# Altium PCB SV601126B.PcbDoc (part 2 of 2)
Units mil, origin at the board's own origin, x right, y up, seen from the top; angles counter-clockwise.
Board outline 2770 x 1865 mil, 4 copper layers (Top Layer, MidLayer1, MidLayer2, Bottom Layer), stack 61.2 mil thick; 102 components, 62 nets, 339 pads, 118 vias.
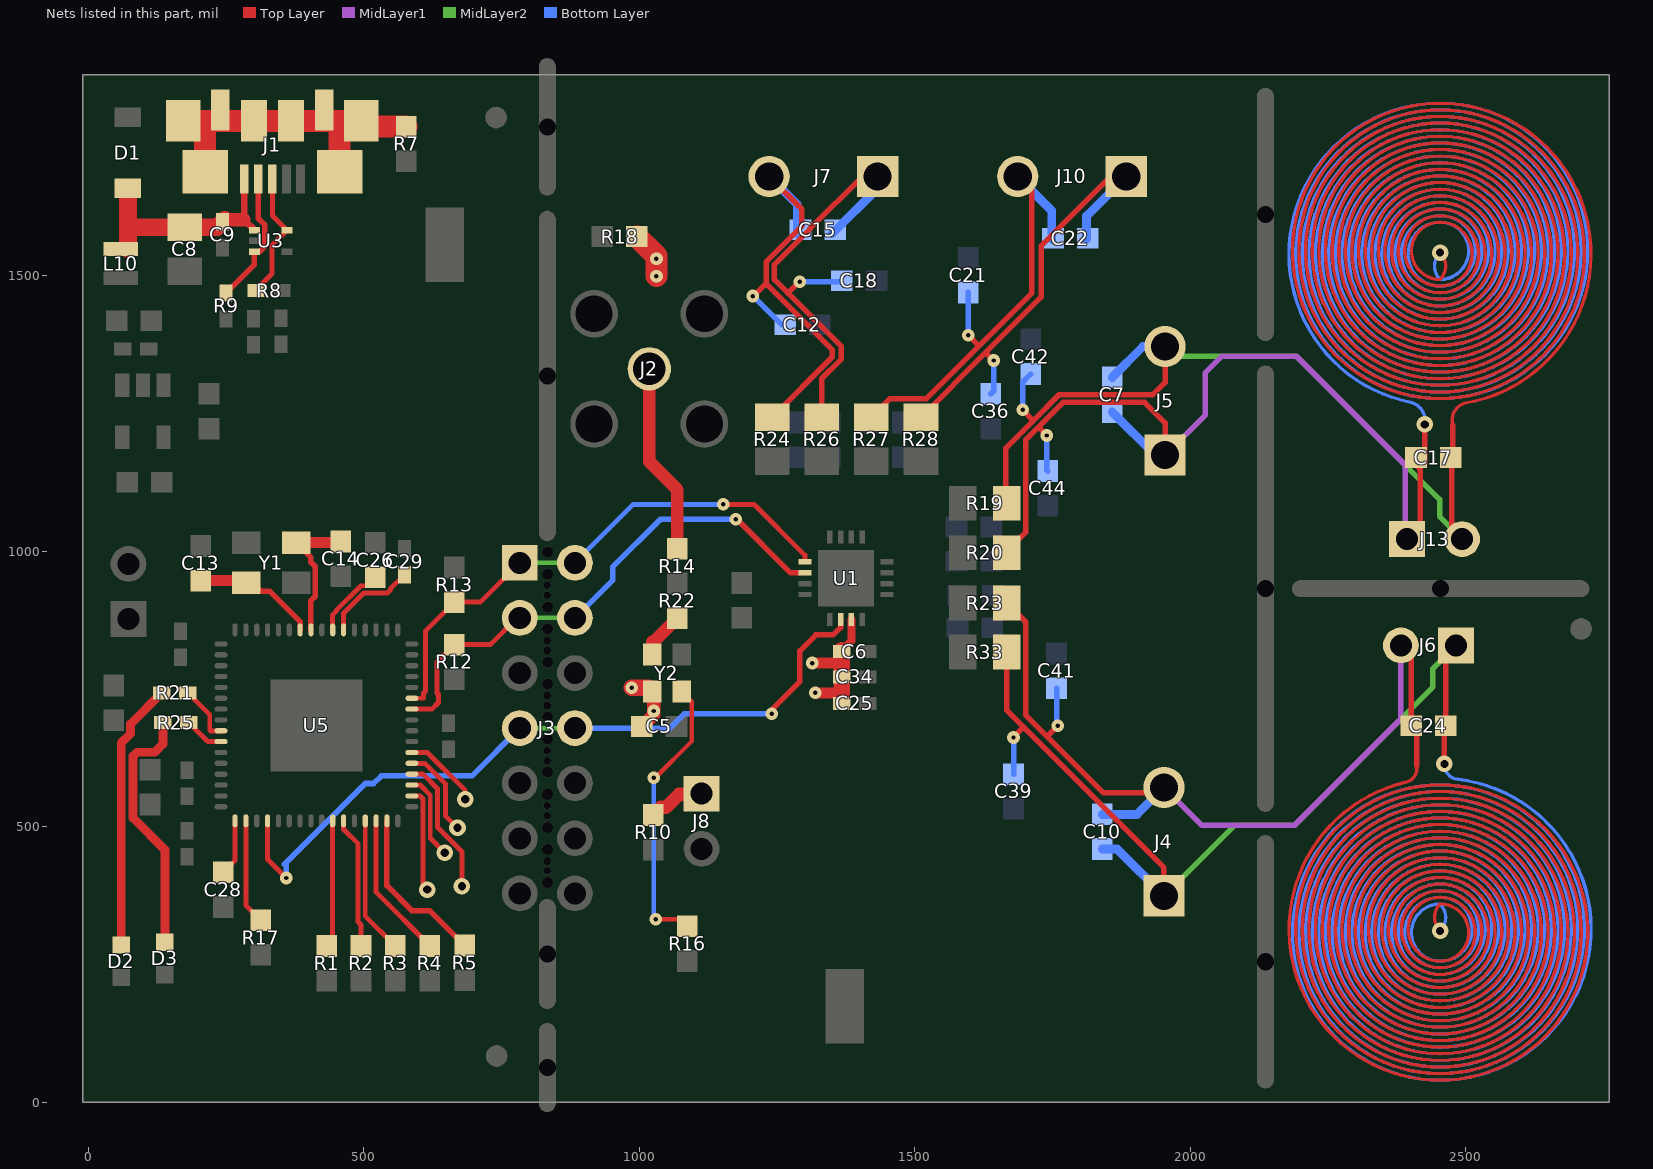
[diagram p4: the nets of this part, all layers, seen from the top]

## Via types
v1: diameter 23, hole 8, Top Layer to Bottom Layer, tented both sides, 79 vias
v2: diameter 19.68, hole 7.87, Top Layer to Bottom Layer, 18 vias
v3: diameter 20, hole 8, Top Layer to Bottom Layer, tented both sides, 8 vias
v4: diameter 30, hole 15, Top Layer to Bottom Layer, 5 vias
v5: diameter 30, hole 15, Top Layer to Bottom Layer, tented both sides, 4 vias
v6: diameter 50, hole 25, Top Layer to Bottom Layer, 2 vias
v7: diameter 50, hole 28, Top Layer to Bottom Layer, 2 vias

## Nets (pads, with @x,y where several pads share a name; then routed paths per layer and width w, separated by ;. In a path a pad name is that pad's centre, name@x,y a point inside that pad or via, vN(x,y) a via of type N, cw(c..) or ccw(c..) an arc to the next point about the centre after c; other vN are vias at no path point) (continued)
NetC7_1: C7.1 C7.2 C17.1 C17.2 C42.2 C44.1 J5.1 J5.2 J13.1 J13.2 R19.2 R20.2 | length 42477.4
  Top Layer w6: v5(2453,1542) cw(c2428.5,1517.5) 2453,1493 cw(c2453,1545) 2453,1597 cw(c2453,1539) 2453,1481 cw(c2453,1545) 2453,1609 cw(c2453,1539) 2453,1469 cw(c2453,1545) 2453,1621 cw(c2453,1539) 2453,1457 cw(c2453,1545) 2453,1633 cw(c2453,1539) 2453,1445 cw(c2453,1545) 2453,1645 cw(c2453,1539) 2453,1433 cw(c2453,1545) 2453,1657 cw(c2453,1539) 2453,1421 cw(c2453,1545) 2453,1669 cw(c2453,1539) 2453,1409 cw(c2453,1545) 2453,1681 cw(c2453,1539) 2453,1397 cw(c2453,1545) 2453,1693 cw(c2453,1539) 2453,1385 cw(c2453,1545) 2453,1705 cw(c2453,1539) 2453,1373 cw(c2453,1545) 2453,1717 cw(c2453,1539) 2453,1361 cw(c2453,1545) 2453,1729 cw(c2453,1539) 2453,1349 cw(c2453,1545) 2453,1741 cw(c2453,1539) 2453,1337 cw(c2453,1545) 2453,1753 cw(c2453,1539) 2453,1325 cw(c2453,1545) 2453,1765 cw(c2453,1539) 2453,1313 cw(c2453,1545) 2453,1777 cw(c2453,1539) 2453,1301 cw(c2453,1545) 2453,1789 cw(c2453,1539) 2453,1289 cw(c2453,1545) 2453,1801 cw(c2453,1539) 2453,1277 cw(c2453,1545) 2453,1813 cw(c2453,1539) 2498.53,1268.81 ccw(c2507.17,1237.64) 2476,1229
  Top Layer w10: R20.2@1667,997 1667,1000 1701,1034 1701,1202 1724,1225 ; R19.2@1667,1087 1665,1089 1665,1187 1716.5,1238.5 ; v1@1696,1256 1713.5,1238.5 1716.5,1238.5 ; v1(1739,1210) 1724,1225 ; J5.1@1954,1174.57 1954,1233 1917,1270 1769,1270 1724,1225 ; J5.2@1954,1371.43 1954,1306 1932,1284 1762,1284 1716.5,1238.5 ; J13.1@2392,1003 2392,1004 2417,1029 2417,1149.5 C17.1@2411.5,1155 ; C17.1@2425,1158.5 v5(2425,1230) ; J13.2@2474.5,1020.5 C17.2@2474.5,1155 ; C17.2@2476,1163.5 2476,1229 ; J13.2@2485,1010 J13.2@2492,1003
  MidLayer1 w10: J5.1@1954,1174.57 2027,1247.57 2027,1324 2057,1354 2192,1354 2390,1156 J13.1@2390,1015
  MidLayer2 w10: J5.2@1954,1371.43 1971.43,1354 2192,1354 2452,1094 2452,1063 J13.2@2493,1022
  Bottom Layer w6: v5(2425,1230) ccw(c2392.09,1237.37) 2399.45,1270.28 cw(c2453,1539) 2453,1813 cw(c2453,1545) 2453,1277 cw(c2453,1539) 2453,1801 cw(c2453,1545) 2453,1289 cw(c2453,1539) 2453,1789 cw(c2453,1545) 2453,1301 cw(c2453,1539) 2453,1777 cw(c2453,1545) 2453,1313 cw(c2453,1539) 2453,1765 cw(c2453,1545) 2453,1325 cw(c2453,1539) 2453,1753 cw(c2453,1545) 2453,1337 cw(c2453,1539) 2453,1741 cw(c2453,1545) 2453,1349 cw(c2453,1539) 2453,1729 cw(c2453,1545) 2453,1361 cw(c2453,1539) 2453,1717 cw(c2453,1545) 2453,1373 cw(c2453,1539) 2453,1705 cw(c2453,1545) 2453,1385 cw(c2453,1539) 2453,1693 cw(c2453,1545) 2453,1397 cw(c2453,1539) 2453,1681 cw(c2453,1545) 2453,1409 cw(c2453,1539) 2453,1669 cw(c2453,1545) 2453,1421 cw(c2453,1539) 2453,1657 cw(c2453,1545) 2453,1433 cw(c2453,1539) 2453,1645 cw(c2453,1545) 2453,1445 cw(c2453,1539) 2453,1633 cw(c2453,1545) 2453,1457 cw(c2453,1539) 2453,1621 cw(c2453,1545) 2453,1469 cw(c2453,1539) 2453,1609 cw(c2453,1545) 2453,1481 cw(c2453,1539) 2453,1597 cw(c2453,1545) 2453,1493 cw(c2477.5,1517.5) v5(2453,1542)
  Bottom Layer w10: v1(1696,1257) 1696,1307.5 C42.2@1710,1321.5 ; v1(1739,1210) 1739,1147.5 C44.1@1741,1145.5 ; J13.2@2476.33,1012.08 J13.2@2486,1012
  Bottom Layer w16: C7.2@1858,1252.5 1935.93,1174.57 J5.1@1954,1174.57 ; C7.1@1858,1315.5 1913.93,1371.43 J5.2@1954,1371.43
NetC10_1: C10.1 C10.2 C24.1 C24.2 C39.2 C41.1 J4.1 J4.2 J6.1 J6.2 R23.2 R33.2 | length 42470.3
  Top Layer w6: 2410.37,610.97 cw(c2385.52,605.69) 2390.8,580.85 ccw(c2453,314) 2453,40 ccw(c2453,308) 2453,576 ccw(c2453,314) 2453,52 ccw(c2453,308) 2453,564 ccw(c2453,314) 2453,64 ccw(c2453,308) 2453,552 ccw(c2453,314) 2453,76 ccw(c2453,308) 2453,540 ccw(c2453,314) 2453,88 ccw(c2453,308) 2453,528 ccw(c2453,314) 2453,100 ccw(c2453,308) 2453,516 ccw(c2453,314) 2453,112 ccw(c2453,308) 2453,504 ccw(c2453,314) 2453,124 ccw(c2453,308) 2453,492 ccw(c2453,314) 2453,136 ccw(c2453,308) 2453,480 ccw(c2453,314) 2453,148 ccw(c2453,308) 2453,468 ccw(c2453,314) 2453,160 ccw(c2453,308) 2453,456 ccw(c2453,314) 2453,172 ccw(c2453,308) 2453,444 ccw(c2453,314) 2453,184 ccw(c2453,308) 2453,432 ccw(c2453,314) 2453,196 ccw(c2453,308) 2453,420 ccw(c2453,314) 2453,208 ccw(c2453,308) 2453,408 ccw(c2453,314) 2453,220 ccw(c2453,308) 2453,396 ccw(c2453,314) 2453,232 ccw(c2453,308) 2453,384 ccw(c2453,314) 2453,244 ccw(c2453,308) 2453,372 ccw(c2453,314) 2453,256 ccw(c2453,308) 2453,360 ccw(c2477.5,335.5) v5(2453,311)
  Top Layer w10: R33.2@1667,817 1667,711 1698,680 ; R23.2@1667,906 1701,872 1701,703 1740,664 ; v1@1679,663 1696,680 1698,680 ; v1(1759,683) 1740,664 ; J4.2@1938,571.43 1938,561.53 J4.2@1942.1,561.53 ; J4.1@1952,380 1952,426 1698,680 ; J4.2@1952,571.43 J4.2@1952,576 ; J4.2@1957.8,557.43 1942.1,557.43 J4.2@1942.1,561.53 ; J6.2@2382,829 2400.5,810.5 C24.1@2400.5,684 ; 2410.37,610.97 C24.1@2410.37,673.14 ; v5(2461,614) C24.2@2461,681.5 ; C24.2@2463.5,683 2463.5,684 2463.5,810.5 J6.1@2482,829 ; 1740,664 1842.47,561.53 J4.2@1942.1,561.53
  MidLayer1 w10: J4.2@1952,571.43 2021,502.43 2188.43,502.43 2382,696 J6.2@2382,829
  MidLayer2 w10: J4.1@1952,374.57 2079.85,502.43 2188.43,502.43 2440,754 2440,787 J6.1@2482,829
  Bottom Layer w6: v5(2453,311) ccw(c2428.5,335.5) 2453,360 ccw(c2453,308) 2453,256 ccw(c2453,314) 2453,372 ccw(c2453,308) 2453,244 ccw(c2453,314) 2453,384 ccw(c2453,308) 2453,232 ccw(c2453,314) 2453,396 ccw(c2453,308) 2453,220 ccw(c2453,314) 2453,408 ccw(c2453,308) 2453,208 ccw(c2453,314) 2453,420 ccw(c2453,308) 2453,196 ccw(c2453,314) 2453,432 ccw(c2453,308) 2453,184 ccw(c2453,314) 2453,444 ccw(c2453,308) 2453,172 ccw(c2453,314) 2453,456 ccw(c2453,308) 2453,160 ccw(c2453,314) 2453,468 ccw(c2453,308) 2453,148 ccw(c2453,314) 2453,480 ccw(c2453,308) 2453,136 ccw(c2453,314) 2453,492 ccw(c2453,308) 2453,124 ccw(c2453,314) 2453,504 ccw(c2453,308) 2453,112 ccw(c2453,314) 2453,516 ccw(c2453,308) 2453,100 ccw(c2453,314) 2453,528 ccw(c2453,308) 2453,88 ccw(c2453,314) 2453,540 ccw(c2453,308) 2453,76 ccw(c2453,314) 2453,552 ccw(c2453,308) 2453,64 ccw(c2453,314) 2453,564 ccw(c2453,308) 2453,52 ccw(c2453,314) 2453,576 ccw(c2453,308) 2453,40 ccw(c2453,314) 2486,586.01 cw(c2487.5,612.5) v5(2461,614)
  Bottom Layer w10: C39.2@1679,595.5 v1(1679,662) ; C41.1@1757,751.5 1757,685 v1(1759,683) ; J6.2@2382,829 J6.2@2396,829 ; J6.1@2464,829 J6.1@2479.28,829 ; J6.1@2480.64,830.36 J6.1@2479.28,829 ; J6.1@2482,829 J6.1@2479.28,829
  Bottom Layer w16: C10.2@1840,459.5 1867.07,459.5 J4.1@1952,374.57 ; C10.1@1840,522.5 1903.07,522.5 J4.2@1952,571.43
NetC12_2: C12.2 C15.1 J7.2 R24.2 | length 814.8
  Top Layer w10: v1@1206.76,1463 1229.88,1486.12 ; J7.2@1235.57,1680 1295,1620.57 1295,1590 1229.88,1524.88 1229.88,1486.12 ; R24.2@1241,1243 1350,1352 1350,1366 1229.88,1486.12
  Bottom Layer w10: v1(1206,1463) C12.2@1258,1411
  Bottom Layer w16: J7.2@1235.57,1680 1286.5,1629.07 C15.1@1286.5,1576
NetC13_2: C13.2 U5.58 Y1.3 | length 226.3
  Top Layer w10: Y1.3@286.72,942.58 299.11,942.58 314.44,927.26 329.64,927.26 384.46,872.43 U5.58@384.46,857.23
  Top Layer w20: C13.2@204,946.5 282.8,946.5 Y1.3@286.72,942.58
NetC14_2: C14.2 U5.57 Y1.1 | length 257.3
  Top Layer w10: Y1.1@377.28,1015.42 404.15,988.54 404.15,979.96 411.87,972.25 411.87,918.19 404.15,910.47 U5.57@404.15,857.23
  Top Layer w20: Y1.1@377.28,1015.42 455.92,1015.42 C14.2@458,1017.5
NetC15_2: C15.2 C18.1 J7.1 R26.2 | length 835.8
  Top Layer w10: v1@1289,1488 1269.5,1468.5 ; 1309,1584.2 1245,1520.2 1245,1493 1269.5,1468.5 ; 1309,1584.4 1404.6,1680 J7.1@1432.43,1680 ; R26.2@1331,1243 1331,1313.2 1366,1348.2 1366,1372 1269.5,1468.5
  Bottom Layer w10: v1(1291,1489) C18.1@1365.5,1489
  Bottom Layer w16: C15.2@1349.5,1576 1432.43,1658.93 J7.1@1432.43,1680
NetC21_2: C21.2 C22.1 J10.2 R27.2 | length 851.4
  Top Layer w10: R27.2@1421,1243 1455,1277 1521,1277 1616.5,1372.5 ; v1(1597,1392) 1615.5,1373.5 1615.5,1372.5 1616.5,1372.5 ; J10.2@1688.15,1680 1712,1656.15 1712,1468 1616.5,1372.5
  Bottom Layer w10: v1(1597,1392) C21.2@1597,1469.5
  Bottom Layer w16: J10.2@1686.57,1680 1748.5,1618.07 C22.1@1748.5,1566
NetC22_2: C22.2 C36.1 J10.1 R28.2 | length 832.1
  Top Layer w10: R28.2@1511,1243 1628.5,1360.5 ; v1@1640,1349 1628.5,1360.5 ; J10.1@1885,1680 1855,1680 1729,1554 1729,1461 1628.5,1360.5
  Bottom Layer w10: C36.1@1638,1285.5 1643,1290.5 v1(1643,1346)
  Bottom Layer w16: C22.2@1811.5,1566 1811.5,1608.07 J10.1@1883.43,1680
NetC26_2: C26.2 U5.55 | length 140.8
  Top Layer w9: U5.55@443.54,857.23 443.54,884.53 450.22,891.22 450.22,892.61 494.93,937.32 517.79,937.32 521,940.53 C26.2@521,952.5
NetC28_1: C28.1 U5.17 | length 102.3
  Top Layer w9: C28.1@245,417.5 266.5,439 266.5,510.6 U5.17@266.33,510.77
NetD2_1: D2.1 R21.2 | length 487.9
  Top Layer w16: D2.1@60,285.53 60,652.15 76.7,668.85 76.7,686.32 R21.2@133.38,743
NetD3_1: D3.1 R25.2 | length 463.6
  Top Layer w16: R25.2@135.38,689 135.38,650.13 120.43,635.18 88.33,635.18 81.3,628.15 81.3,515.85 139,458.15 139,304.53 D3.1@139,290.53
NetJ1_2: J1.2 R9.1 U3.3 | length 246.1
  Top Layer w10: R9.1@250,1468.62 301.47,1520.09 U3.3@301.47,1543.32 310.26,1543.32 320.31,1553.37 320.31,1592.32 308.41,1604.22 J1.2@308.41,1675.49
NetJ1_3: J1.3 R8.1 U3.5 | length 236.7
  Top Layer w9: R8.1@304.38,1473 304.38,1474.47 333.81,1503.91 333.81,1555.97 U3.5@360.53,1582.69 334,1609.21 J1.3@334,1675.49
NetJ1_6: J1.6 J1.7 J1.8 J1.9 J1.10 J1.11 J1.12 J1.13 R7.2 | length 725
  Top Layer w40: J1.13@178,1781 J1.8@495.42,1781 ; J1.7@211.95,1688.48 211.95,1779.95 ; 211.95,1781 J1.11@300.54,1781 J1.10@367.46,1781 ; J1.6@456.05,1688.48 456.05,1777.95 ; J1.8@505.92,1770.5 R7.2@577,1770.5
NetJ2_1: J2.1 R14.2 | length 347.6
  Top Layer w23: J2.1@1018,1331 1018,1162.5 1069,1111.5 R14.2@1069,1004.5
NetR1_1: R1.1 U5.26 | length 231.6
  Top Layer w9: R1.1@433,283.5 443.54,294.03 U5.26@443.54,510.77
NetR2_1: R2.1 U5.27 | length 240.4
  Top Layer w9: U5.27@463.22,510.77 463.22,495.57 489.61,469.19 489.61,327.11 495,321.72 R2.1@495,283.5
NetR3_1: R3.1 U5.29 | length 249.8
  Top Layer w9: U5.29@502.61,510.77 502.61,337.89 R3.1@557,283.5
NetR4_1: R4.1 U5.30 | length 267.7
  Top Layer w9: U5.30@522.3,510.77 522.3,381.2 R4.1@620,283.5
NetR5_1: R5.1 U5.31 | length 303.7
  Top Layer w10: U5.31@541.98,510.77 541.98,393.02 587,348 619.5,348 R5.1@683,284.5
NetR16_2: R16.2 Y2.1 | length 515
  Top Layer w8: v1(1026.4,588.82) 1028.71,588.82 1095.43,655.55 1095.43,726.68 Y2.1@1076.57,745.54 ; v1(1030,332) 1074.5,332 R16.2@1087,319.5
  Bottom Layer w8: v1(1026.4,588.82) 1026.4,335.6 v1(1030,332)
NetR17_1: R17.1 U5.18 | length 191.5
  Top Layer w9: U5.18@286.01,510.77 286.01,357.48 R17.1@313,330.5
NetR21_1: R21.1 U5.9 | length 104.7
  Top Layer w9: R21.1@180.62,743 220.46,703.16 220.46,675.85 222.16,674.16 U5.9@240.77,674.16
NetR22_1: R22.1 Y2.3 | length 96.8
  Top Layer w10: R22.1@1069,878.5 R22.1@1076.46,871.04
  Top Layer w23: Y2.3@1023.43,812.46 1023.43,835.15 1025.65,835.15 R22.1@1069,878.5
NetR25_1: R25.1 U5.10 | length 72.5
  Top Layer w9: R25.1@182.62,689 217.15,654.47 U5.10@240.77,654.47
P3.0: U5.34 | length 190.2
  Top Layer w9: U5.34@587.23,556.05 601.95,556.05 607.54,550.46 607.54,393.46 v4(615,386)
P3.1: U5.35 | length 156.3
  Top Layer w9: U5.35@587.23,575.73 602.27,575.73 620.54,557.46 620.54,479.46 v4(647,453)
P3.2: U5.36 | length 252.9
  Top Layer w9: U5.36@587.23,595.42 607.58,595.42 633.54,569.46 633.54,499.69 678,455.23 v4(678,392)
P3.3: U5.37 | length 165.3
  Top Layer w9: U5.37@587.23,615.1 610.9,615.1 648,578 648,520 v4(670,498)
P3.4: U5.38 | length 141.3
  Top Layer w9: U5.38@587.23,634.79 615.21,634.79 684,566 v4(684,550)
SCL: J3.1 J3.2 R13.1 U1.1 U5.43 | length 978.6
  Top Layer w9: U5.43@587.23,733.21 608.21,733.21 608.21,742.44 611.54,745.76 611.54,855.04 R13.1@664,907.5 711.5,907.5 J3.1@783,979 ; v1(1152,1085) 1208,1085 1300.2,992.8 U1.1@1300.2,980.53
  MidLayer2 w8: J3.1@783,979 J3.2@883,979
  Bottom Layer w9: J3.2@883,979 989,1085 v1(1152,1085)
SD: J3.7 J3.8 U1.6 U5.20 | length 1373.8
  Top Layer w9: U5.20@325.39,510.77 325.39,440.61 v1(359,407)
  Top Layer w10: v1(1240,705) 1240,712 1284.39,756.39 1291.2,763.2 1291.2,819 1320.2,848 1351.77,848 1365.16,861.39 U1.6@1365.16,876.2
  MidLayer2 w8: J3.7@783,679 J3.8@873,679
  Bottom Layer w10: v1(359,407) 359,429.08 356.08,432 502.58,578.5 517.8,578.5 531.8,592.5 696.5,592.5 J3.7@783,679 ; J3.8@883,679 1052,679 1053.61,677.39 1081.23,705 v1(1240,705)
SDA: J3.3 J3.4 R12.1 U1.2 U5.42 | length 948.1
  Top Layer w9: U5.42@587.23,713.53 623.53,713.53 635.46,725.46 635.46,739.98 632.8,742.64 632.8,799.3 R12.1@664,830.5 729.5,830.5 778,879 J3.3@783,879
  Top Layer w10: v1(1175,1058) 1177,1058 1274.47,960.53 U1.2@1291.2,960.53
  MidLayer2 w8: J3.3@783,879 J3.4@883,879
  Bottom Layer w10: J3.4@883,879 952,948 952,972 1038,1058 v1(1175,1058)
VBUS: C8.1 C9.1 D1.1 J1.1 L10.1 U3.1 | length 429.4
  Top Layer w12: J1.1@282.82,1675.49 282.82,1601.34 U3.1@301.47,1582.69
  Top Layer w24: C9.1@247.72,1601.34 282.82,1601.34
  Top Layer w32: L10.1@71,1548.57 72,1549.57 72,1593.32 ; D1.1@72,1658.53 72,1593.32 ; C9.1@247.72,1601.34 C9.1@244,1597.62 234.38,1588 C8.1@175,1588 77.32,1588 72,1593.32
VDD: C5.1 C6.1 C25.1 C34.1 J8.1 R10.2 R18.2 U1.7 Y2.4 | length 547.1
  Top Layer w14: C6.1@1367.38,820 1384.84,837.46 U1.7@1384.84,876.2
  Top Layer w20: v1(1314,797) 1364.88,797 1367.38,799.5 ; v1(1319,743) 1365.88,743 1367.38,744.5
  Top Layer w24: C5.1@1004.5,682 1026,703.5 1026,742.96 Y2.4@1023.43,745.54 ; R10.2@1025,521.5 1038.83,535.32 1048.56,535.32 1072.42,559.18 1113,559.18 J8.1@1113,560
  Top Layer w30: v1(986,752) 1016.96,752 Y2.4@1023.43,745.54 ; 1367.38,744.5 C34.1@1367.38,772 1367.38,799.5 C6.1@1367.38,820
  Top Layer w40: R18.2@995.5,1571 1031,1535.5 v1(1031,1499)
  other v1: 1026,710 1031,1530.77
VUSB: C29.1 U5.54 | length 171.2
  Top Layer w9: U5.54@463.22,857.23 463.22,887.22 500.32,924.32 543.22,924.32 548.2,929.3 548.2,931.58 C29.1@574,957.38
pads on no net: FID1.1 FID2.1 FID3.1 J1.4 LBL1.0 U3.2 U5.1 U5.2 U5.3 U5.4 U5.5 U5.6 U5.7 U5.8 U5.12 U5.13 U5.22 U5.23 U5.24 U5.25 U5.28 U5.32 U5.33 U5.41 U5.44 U5.45 U5.46 U5.47 U5.48

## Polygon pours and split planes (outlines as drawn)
GND on MidLayer1 "Bottom Layer-No Net" (solid, pour order 9): 20,20 793,20 793,1840 20,1840 20,20
GND on MidLayer1 "Bottom Layer-No Net" (solid, remove dead copper, pour order 12): 875,35 2100,35 2100,1840 875,1840 875,35
+3.3V on MidLayer2 "Bottom Layer-No Net" (solid, pour order 7): 20,770 790,770 790,1840 20,1840
+3.3V on MidLayer2 "Bottom Layer-No Net" (solid, pour order 8): 17,17 791,17 791,770.5 17,770.5 17,17
+3.3V on MidLayer2 "Bottom Layer-No Net" (solid, remove dead copper, pour order 11): 875,35 2100,35 2100,1840 875,1840 875,35
VDD on MidLayer2 "Bottom Layer-No Net" (solid, remove dead copper, pour order 10): 972.46,510 1600,510 1600,1725.95 972.46,1725.95
GND on Bottom Layer "Bottom Layer-No Net 1" (solid, remove dead copper, pour order 8): 1782,1549.3 901,1549.3 901,502 1782,502

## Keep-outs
Keep-Out Layer:
  lines w8: -15,-5 2765,-5 2765,1870 -15,1870 -15,-5
  text ".Layer_Name" at 577,-858.49 h60

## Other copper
Top Layer:
  text ".Layer_Name" at 577,-858.49 h60
MidLayer1:
  pour cut-out: 154.5,894 154.7,894.2 154.7,1052.87 485.63,1052.87 497.5,1040.99 497.5,888
MidLayer2:
  pour cut-out: 866.5,1483.11 866.61,1483 1172.5,1483 1172.5,1175 1171.5,1174 866.5,1174
  pour cut-out: 154.5,894 154.7,894.2 154.7,1052.87 485.63,1052.87 497.5,1040.99 497.5,888
Bottom Layer:
  text ".Layer_Name" at 577,-858.49 h60
Multi-Layer:
  pour cut-out: 2453,-239 cw(c2453,311) 1903,311 cw(c2453,311) 2453,861 cw(c2453,311) 3003,311 cw(c2453,311)
  pour cut-out: 1903,1542 ccw(c2453,1542) 2453,992 ccw(c2453,1542) 3003,1542 ccw(c2453,1542) 2453,2092 ccw(c2453,1542)

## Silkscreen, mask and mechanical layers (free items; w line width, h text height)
Top Overlay:
  lines w10: 1223,693 1550,693 1550,1106 1223,1106 1223,693
  text "GND" at 897,1808 h30
  text "CH3" at 1274.37,1429.68 h60
  text "CH2" at 1582,1430 h60
  text "GND" at 602,1425 h30
  text "SENSOR CH1" at 2285,1264 h55 r90
  text "+5V" at 417,1165 h30
  text "LDC" at 1235,1050 h40
  text "CH1" at 1873,977 h60
  text "or" at 1010,943 h30 r90
  text "SBW" at 161,898 h25 r90
  text "+3.3V" at 1204,438 h30 r90
  text "GND" at 1338,289 h30
  text "GND" at 891,255 h30
  text "CH0" at 1864,158 h60
  text "SENSOR CH0" at 2285,64 h55 r90
  text "GND" at 179,52 h30
  text "ACLK" at 360,43 h30 r90
  text ".Layer_Name" at 577,-858.49 h60
  text "CH0" at 2292,-1832 h60
Bottom Overlay:
  region: 267,589 267,889 167,889 167,589
  text ".PRJ_Number" at 267,1805 h60 r90
  text "0.15mm trace width" at 2630,1804 h40 r90
  text "0.15mm trace spacing" at 2688,1804 h40 r90
  text "19 turns/layer" at 2514,1803 h40 r90
  text "2 layers" at 2572,1803 h40 r90
  text "SENSOR: 13.9mm" at 2456,1802 h40 r90
  text ".PCB_Rev" at 267,1292 h60 r90
  text "TCK" at 100,1042 h25
  text "SCL" at 1015,968 h30
  text "SDA" at 1024.37,865 h30
  text "TDIO" at 113,791 h25
  text "©" at 2613,768 h105 r90
  text "ADDR" at 1060.3,762 h30
  text "MADE IN U.S." at 2717,760 h60 r90
  text ".CopyrightYear" at 2086,677 h60 r90
  text "SD" at 1010,660 h30
  text "INTB" at 1045,565 h30
  text "GND" at 1018.25,469.61 h30
  text "3.3V" at 1046,363 h30
  text ".Layer_Name" at 577,-858.49 h60
Top Paste:
  text ".Layer_Name" at 577,-858.49 h60
Bottom Paste:
  text ".Layer_Name" at 577,-858.49 h60
Top Solder:
  text ".Layer_Name" at 577,-858.49 h60
  text ".Layer_Name" at 577,-858.49 h60
Bottom Solder:
  text ".Layer_Name" at 577,-858.49 h60
Drill Guide:
  text ".Layer_Name" at 577,-858.49 h60
M1 Board Outline:
  the board outline again, w8
  text ".Layer_Name" at 577,-858.49 h60
M2 Board Dimensions:
  rectangle: 124.5,-410.5 499.5,-285.5
  rectangle: -0.5,-285.5 124.5,-160.5
  lines w7: -0.5,-285.5 999.5,-285.5 ; 124.5,-410.5 124.5,-160.5 ; 249.5,-410.5 249.5,-160.5 ; 499.5,-410.5 499.5,-160.5 ; 749.5,-410.5 749.5,-160.5 ; -0.5,-410.5 -0.5,-160.5 999.5,-160.5 999.5,-410.5 -0.5,-410.5
  lines w10: -0.5,-475.5 -0.5,-455.5 ; 59.5,-485.5 -0.5,-465.5 ; 59.5,-445.5 -0.5,-465.5 ; 223.58,-465.5 -0.5,-465.5 ; 775.42,-465.5 999.5,-465.5 ; 939.5,-485.5 999.5,-465.5 ; 939.5,-445.5 999.5,-465.5 ; 999.5,-475.5 999.5,-455.5
  text "1000 (mil)" at 233.58,-501.49 h60
  text ".Layer_Name" at 577,-858.49 h60
M3 3D STEP Top:
  text ".Layer_Name" at 577,-858.49 h60
M4 3D STEP Bottom:
  text ".Layer_Name" at 577,-858.49 h60
M5 Assembly Top:
  lines w10: -292,-930.17 6308,-930.17 ; -292,-726.83 6310,-726.83 ; -292,-523.5 -292,-1133.5 3713,-1133.5 6310,-1133.5 6310,-523.5 -291.5,-523.5 -291.5,-1133.5 1284,-1133.5 ; 2173,-1133.5 2173,-523.5 ; 3440,-726.83 3440,-523.5 ; 4280,-726.83 4280,-523.5 ; 4902,-1140 4902,-937.17
  text "COMPONENTS MARKED 'DNP' SHOULD NOT BE POPULATED." at 1153.5,-318.5 h60
  text "ASSEMBLY VARIANT:" at 1153,-434 h60
  text ".VariantName" at 2189,-434 h60
  text "PCB VIEWED FROM TOP SIDE" at -228.5,-655.67 h60
  text "BOARD #:" at 2248,-655.67 h60
  text ".PRJ_Number" at 2793.5,-655.67 h60
  text "REV:" at 3638,-655.67 h60
  text ".PCB_Rev" at 3929.5,-655.67 h60
  text "SVN REV:" at 4476,-655.67 h60
  text ".VersionControl_RevNumber" at 4982,-655.67 h60
  text "IGNORE ->" at -228.5,-858.49 h60
  text "PLOT NAME =" at -228.5,-1064.34 h60
  text ".plot_File_Name" at 577,-1064.34 h60
  text "GENERATED    :" at 2250,-1064.34 h60
  text ".Print_Date" at 3119.5,-1064.34 h60
  text ".Print_Time" at 3848.5,-1064.34 h60
  text "TEXAS INSTRUMENTS" at 5113,-1064.34 h60
M6 Assembly Bottom:
  lines w10: -292.5,-727.33 6309.5,-727.33 ; -290.5,-930.67 6309.5,-930.67 ; 1115.5,-1140.5 1115.5,-937.67 ; 1737.5,-727.33 1737.5,-524 ; 2577.5,-727.33 2577.5,-524 ; 3844.5,-1134 3844.5,-524 ; 4733.5,-1134 6309,-1134 6309,-524 -292.5,-524 -292.5,-1134 2304.5,-1134 6309.5,-1134 6309.5,-524
  text "COMPONENTS MARKED 'DNP' SHOULD NOT BE POPULATED." at 6102,-318 h60
  text ".VariantName" at 5058,-434 h60
  text "ASSEMBLY VARIANT:" at 6097,-434 h60
  text ".VersionControl_RevNumber" at 1035.5,-656.17 h60
  text "SVN REV:" at 1541.5,-656.17 h60
  text ".PCB_Rev" at 2088,-656.17 h60
  text "REV:" at 2379.5,-656.17 h60
  text ".PRJ_Number" at 3224,-656.17 h60
  text "BOARD #:" at 3769.5,-656.17 h60
  text "PCB VIEWED FROM BOTTOM SIDE" at 6246,-656.17 h60
  text "IGNORE ->" at 2547.85,-858.49 h60
  text "TEXAS INSTRUMENTS" at 904.5,-1064.84 h60
  text ".Print_Time" at 2169,-1064.84 h60
  text ".Print_Date" at 2898,-1064.84 h60
  text "GENERATED    :" at 3767.5,-1064.84 h60
  text ".plot_File_Name" at 5440.5,-1064.84 h60
  text "PLOT NAME =" at 6246,-1064.84 h60
M9 Title Sheet:
  drawing of 54 lines, arcs and shapes, not listed
  text "1" at 739.84,8036.5 h70
  text "2" at 3235.5,8036.5 h70
  text "3" at 5724.84,8036.5 h70
  text "4" at 8231.51,8036.5 h70
  text "5" at 10730.5,8036.5 h70
  text "6" at 13235.5,8036.5 h70
  text "A" at -416.5,6893.5 h70
  text "A" at 14383.5,6893.5 h70
  text "B" at -416.5,4513.5 h70
  text "B" at 14383.5,4513.5 h70
  text "C" at -416.5,2138.5 h70
  text "C" at 14383.5,2138.5 h70
  text "PROJECT TITLE:" at 11343.5,277.5 h45
  text ".PRJ_Title" at 11393.5,144.17 h70
  text "DESIGNED FOR:" at 11343.5,-23.5 h45
  text ".PRJ_Customer" at 11393.5,-163.5 h70
  text "D" at -416.5,-231.5 h70
  text "D" at 14383.5,-231.5 h70
  text "FILE NAME:" at 11343.5,-323.5 h45
  text ".PCB_File_Name_No_Path" at 11393.5,-443.5 h70
  text "Texas Instruments (TI) and/or its licensors do not warrant the accuracy or completeness of this specification" at 6374,-605.34 h45
  text "ENGINEER:" at 11343.5,-613.5 h45
  text "LAYOUT BY:" at 12848.5,-613.5 h45
  text "or any information contained therein. TI and/or its licensors do not warrant that this design will meet" at 6329.01,-718 h45
  text ".PRJ_Engineer" at 11393.5,-768.49 h70
  text ".PCB_Layout" at 12899,-768.49 h70
  text "the specifications, will be suitable for your application or fit for any particular purpose, or will operate in" at 6329.01,-830.67 h45
  text ".Layer_Name" at 577,-858.49 h60
  text "ALTIUM DESIGNER VERSION:" at 12848.5,-923.5 h45
  text "an implementation. TI and/or its licensors do not warrant that the design is production worthy. You should" at 6329.01,-943.33 h45
  text "completely validate and test your design implementation to confirm the system functionality for your application." at 6374,-1056 h45
  text ".print_Scale" at 11393.5,-1056.83 h70
  text ".Application_BuildNumber" at 12899,-1056.83 h70
  text "1" at 739.84,-1263.5 h70
  text "2" at 3235.5,-1263.5 h70
  text "3" at 5724.84,-1263.5 h70
  text "4" at 8231.51,-1263.5 h70
  text "5" at 10730.5,-1263.5 h70
  text "6" at 13235.5,-1263.5 h70
M10 Fab Notes:
  drawing of 212 lines, arcs and shapes, not listed
  text "DESIGN INFORMATION" at 12381.02,6810 h60
  text "(REFER ALSO ARRAY/PANEL PROFILING INFORMATION)" at 12019.46,6648.29 h60
  text "BOARD SIZE" at 11333.46,6644 h60
  text "2760MIL" at 11795.78,6516.18 h60
  text "X" at 12301.46,6516.18 h60
  text "1865MIL" at 12532.78,6516.18 h60
  text "Number of Layers :" at 11736.46,6319 h60
  text "4" at 12831.27,6309 h60
  text "MIN. TRACK WIDTH:" at 11736.46,6180 h60
  text "4" at 12832.7,6180 h60
  text "MIL" at 12987.46,6180 h60
  text "MIN. CLEARANCE:" at 11736.46,6048 h60
  text "4" at 12832.7,6048 h60
  text "MIL" at 12987.46,6048 h60
  text "MIN. VIA PAD SIZE:" at 11736.46,5916 h60
  text "20" at 12802.71,5916 h60
  text "MIL" at 12987.46,5916 h60
  text "0.05mm (2MIL)" at 12431.46,5774.29 h60
  text "MINIMUM ANNULAR RING" at 11407.23,5770 h60
  text "EXTERNAL" at 13139.46,5770 h60
  text "PER" at 11607.23,5652 h60
  text "IPC-D-275 CLASS 2 LEVEL C" at 11827.23,5652 h60
  text "MIL, HOLES" at 13315.46,5539.71 h60
  text "+/-" at 12923,5539 h60
  text "+/-" at 13777,5539 h60
  text "REGISTRATION TOLERANCES:" at 11407.23,5534 h60
  text "METAL" at 12607,5534 h60
  text "5" at 13183.2,5534 h60
  text "3" at 14016.2,5534 h60
  text "MIL" at 14132.46,5534 h60
  text "MATERIAL:" at 11332.46,5324.54 h60
  text "FR-4 High Tg" at 12318.9,5184.21 h60
  text "FR-408" at 11753.46,5175.64 h60
  text "X" at 12165.46,5175.64 h60
  text "OTHER" at 13241.46,5175.64 h60
  text "62 MIL (1.6mm) +/-10%" at 12073.56,5012.92 h60
  text "THICKNESS:" at 11407.23,5008.64 h60
  text "X" at 11945.4,5008.64 h60
  text "OTHER" at 13358.46,5008.64 h60
  text "TOLERANCE:" at 11407.23,4850.64 h60
  text "X" at 12246.53,4850.64 h60
  text "ANSI IPC-6012 TYPE 3 CLASS 2" at 12433.48,4850.64 h60
  text "OTHER +/-" at 12433.46,4694.64 h60
  text "BOW & TWIST:" at 11407.23,4537.64 h60
  text "X" at 12246.53,4537.64 h60
  text "ANSI IPC-6012 TYPE 3 CLASS 2" at 12433.48,4537.64 h60
  text "OTHER +/-" at 12433.46,4379.13 h60
  text "COPPER THICKNESS (FINISHED):" at 11332.46,4243.64 h60
  text "1.4MIL (1oz)" at 12212.46,4090.92 h60
  text "2MIL (1.4oz)" at 12979.46,4090.92 h60
  text "2.8MIL (2oz)" at 13706.46,4090.92 h60
  text "OUTER:" at 11689.46,4086.64 h60
  text "X" at 12084,4086 h60
  text "1.4MIL (1oz)" at 12212.46,3933.92 h60
  text "2.8MIL (2oz)" at 12979.46,3933.92 h60
  text "N/A" at 13706,3934.29 h60
  text "INNER SIGNAL:" at 11400.38,3929.64 h60
  text "X" at 12085.42,3929.64 h60
  text "DRILLING:" at 11332.46,3790.64 h60
  text "REFERENCE:" at 11407.23,3673.64 h60
  text "X" at 12055.46,3673.64 h60
  text "AS SHOWN" at 12242.46,3673.64 h60
  text "X" at 12956.46,3673.64 h60
  text "NC_DRILL FILES" at 13093.46,3673.64 h60
  text "PTH MIN COPPER THICKNESS:" at 11407.23,3515.64 h60
  text "X" at 12757.46,3515.64 h60
  text "1MIL" at 12894.46,3515.64 h60
  text "OTHER" at 13391.46,3515.64 h60
  text "BOARD FINISH:" at 11332.46,3356.64 h60
  text "SILKSCREEN:" at 11487.68,3238.64 h60
  text "X" at 12436.46,3238.64 h60
  text "TOP" at 12562.46,3238.64 h60
  text "X" at 12946.46,3238.64 h60
  text "BOTTOM" at 13073.46,3238.64 h60
  text "SILKSCREEN COLOR:" at 11487.68,3071.64 h60
  text "X" at 12435.42,3071.64 h60
  text "WHITE" at 12562.46,3071.64 h60
  text "OTHER" at 13073.46,3071.64 h60
  text "SOLDER RESIST COLOR:" at 11487.68,2901.64 h60
  text "X" at 12055.42,2742.44 h60
  text "GREEN" at 12182.46,2742.44 h60
  text "BLUE" at 12773.46,2742.44 h60
  text "OTHER" at 13311.46,2742.44 h60
  text "IMMERSION GOLD (ENIG)" at 12393.46,2553.92 h60
  text "ENEPIG" at 13731,2550.64 h60
  text "SURFACE FINISH:" at 11332.46,2549.64 h60
  text "X" at 12206.51,2549.64 h60
  text "IMM. TIN/SILVER OR EQUIV" at 11662,2392.64 h60
  text "OTHER" at 13093.46,2392.64 h60
  text "ARRAY/PANEL:" at 11332.46,2213.64 h60
  text "CUT AND TRIM PER MECH LAYER 1" at 12393.46,2209.35 h60
  text "X" at 12209,2062 h60
  text "N.C. ROUTE" at 12393.46,2057.64 h60
  text "V. SCORE" at 13259.46,2057.64 h60
  text "CERTIFICATION:" at 11332.46,1920.64 h60
  text "MATERIALS AND WORKMANSHIP FOR ALL PCBS" at 12057.46,1920.64 h60
  text "TO MEET OR EXCEED THE REQUIREMENTS OF:" at 12057.46,1822.64 h60
  text "X" at 11683.96,1686.13 h60
  text "ANSI IPC-A-600F CLASS ->" at 11822.96,1686.13 h60
  text "X" at 13462.02,1686.13 h60
  text "2" at 13580.96,1686.14 h60
  text "1" at 13265.96,1684.64 h60
  text "3" at 13934.96,1684.64 h60
  text "X" at 11686.02,1526.64 h60
  text "UL 94V-0" at 11822.96,1526.64 h60
  text "X" at 12498.02,1526.64 h60
  text "RoHS" at 12634.96,1526.64 h60
  text "OTHER" at 13279.36,1526.64 h60
  text "PER ORDER" at 13676.42,1526.64 h60
  text "ADDITIONAL REQUIREMENTS:" at 11332.46,1385.64 h60
  text "MICROSECTION:" at 11407.23,1270.64 h60
  text "YES" at 12312.96,1270.64 h60
  text "REQUIRED" at 13174.46,1114.49 h60
  text "BARE BOARD ELEC. TEST:" at 11407.23,1111.64 h60
  text "NONE" at 12712.96,1111.64 h60
  text "X" at 13047.46,1111.64 h60
  text "PER ORDER" at 13766.46,1111.64 h60
  text "MANUFACTURER'S UL:" at 11407.23,954.64 h60
  text "RAIL" at 12572.96,950.35 h60
  text "METAL" at 13064.77,950.35 h60
  text "X" at 13440,950 h60
  text "SILK" at 13576.46,950.35 h60
  text ".Layer_Name" at 577,-858.49 h60
M11 Gerber Information:
  lines w10: -292,-930.17 6308,-930.17 ; -292,-726.83 6310,-726.83 ; -292,-523.5 -292,-1133.5 3713,-1133.5 6310,-1133.5 6310,-523.5 -291.5,-523.5 -291.5,-1133.5 1284,-1133.5 ; 2173,-1133.5 2173,-523.5 ; 3440,-726.83 3440,-523.5 ; 4280,-726.83 4280,-523.5 ; 4902,-1140 4902,-937.17
  text "ALL ARTWORK VIEWED FROM TOP SIDE" at -228.5,-655.67 h60
  text "BOARD #:" at 2248,-655.67 h60
  text ".PRJ_Number" at 2793.5,-655.67 h60
  text "REV:" at 3638,-655.67 h60
  text ".PCB_Rev" at 3929.5,-655.67 h60
  text "SVN REV:" at 4476,-655.67 h60
  text ".VersionControl_RevNumber" at 4982,-655.67 h60
  text "LAYER NAME =" at -228.5,-858.49 h60
  text "PLOT NAME =" at -228.5,-1064.34 h60
  text ".plot_File_Name" at 577,-1064.34 h60
  text "GENERATED    :" at 2250,-1064.34 h60
  text ".Print_Date" at 3119.5,-1064.34 h60
  text ".Print_Time" at 3848.5,-1064.34 h60
  text "TEXAS INSTRUMENTS" at 5113,-1064.34 h60
M12 Stackup:
  lines w6: 11365,7632.25 14230,7632.25 ; 11365,7744.85 14230,7744.85 ; 11286,6907 ccw(c11322,6907) 11322,6871 14235,6871 ccw(c14235,6907) 14271,6907 14271,7902 ccw(c14235,7902) 14235,7938 11322,7938 ccw(c11322,7902) 11286,7902 11286,6907
  text "Layer Stack Up Detail for: SV601147B.PcbDoc" at 11346,7819.02 h58
  text "Layer" at 11365,7702.85 h26
  text "Gerber" at 12072.2,7702.85 h26
  text "Copper" at 12433.65,7702.85 h26
  text "Dielectric" at 12837.55,7702.85 h26
  text "Dielectric" at 13259.64,7702.85 h26
  text "Dielectric" at 13786.9,7702.85 h26
  text "Name" at 11365,7650.85 h26
  text "Document" at 12072.2,7650.85 h26
  text "Thickness" at 12433.65,7650.85 h26
  text "Height" at 12837.55,7650.85 h26
  text "Material" at 13259.64,7650.85 h26
  text "Type" at 13786.9,7650.85 h26
  text "Top Solder Mask" at 11365,7573.68 h36
  text "(.GTS)" at 12072.2,7573.68 h36
  text "0.4mil" at 12837.55,7573.68 h36
  text "Solder Resist" at 13259.64,7573.68 h36
  text "Top Layer" at 11365,7462.53 h36
  text "(.GTL)" at 12072.2,7462.53 h36
  text "1.4mil" at 12433.65,7462.53 h36
  text "12.6mil" at 12837.55,7406.96 h36
  text "FR-4" at 13259.64,7406.96 h36
  text "Core" at 13786.9,7406.96 h36
  text "MidLayer1" at 11365,7351.39 h36
  text "(.G1)" at 12072.2,7351.39 h36
  text "1.4mil" at 12433.65,7351.39 h36
  text "30.4mil" at 12837.55,7295.81 h36
  text "FR-4" at 13259.64,7295.81 h36
  text "PrePreg" at 13786.9,7295.81 h36
  text "MidLayer2" at 11365,7240.24 h36
  text "(.G2)" at 12072.2,7240.24 h36
  text "1.4mil" at 12433.65,7240.24 h36
  text "12.6mil" at 12837.55,7184.67 h36
  text "FR-4" at 13259.64,7184.67 h36
  text "Core" at 13786.9,7184.67 h36
  text "Bottom Layer" at 11365,7129.09 h36
  text "(.GBL)" at 12072.2,7129.09 h36
  text "1.4mil" at 12433.65,7129.09 h36
  text "Bottom Solder Mask" at 11365,7017.95 h36
  text "(.GBS)" at 12072.2,7017.95 h36
  text "0.4mil" at 12837.55,7017.95 h36
  text "Solder Resist" at 13259.64,7017.95 h36
  text ".Layer_Name" at 577,-858.49 h60
M13 Component Bodies Top:
  text ".Layer_Name" at 577,-858.49 h60
M14 Component Bodies Bottom:
  text ".Layer_Name" at 577,-858.49 h60
M15 Courtyards Top:
  text ".Layer_Name" at 577,-858.49 h60
M16 Courtyards Bottom:
  text ".Layer_Name" at 577,-858.49 h60
Drill Drawing:
  text ".legend" at 3686,1076 h40
  text ".Layer_Name" at 577,-858.49 h60

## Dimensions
0,0 to 2760,0 on M2 Board Dimensions
0,0 to -10,1865 on M2 Board Dimensions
